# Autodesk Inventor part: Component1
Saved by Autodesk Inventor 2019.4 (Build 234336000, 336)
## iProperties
Created: 2020-06
Part Number: Component1
Material: Generic
Document SubType Name: Modeling
Designer: Administrator
Density: 1 g/cm^3
Appearance: Default
Title: Component1
Author: Administrator
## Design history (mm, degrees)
